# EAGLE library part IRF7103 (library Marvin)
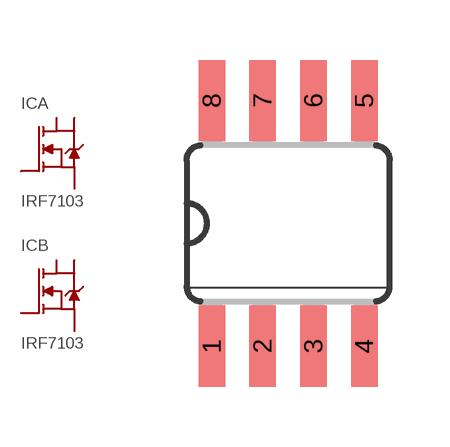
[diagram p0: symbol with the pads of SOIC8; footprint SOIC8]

Designator prefix IC; gates A=IRF7103 B=IRF7103

## IRF7103  [SOIC8]
1  A:S  pas
2  A:G  pas
3  B:S  pas
4  B:G  pas
5  B:D2  pas
6  B:D1  pas
7  A:D2  pas
8  A:D1  pas

## Footprint SOIC8 (pad centres in mm)
smd 0.66 x 2.032: 1 -1.905,-3.073; 2 -0.635,-3.073; 3 0.635,-3.073; 4 1.905,-3.073; 5 1.905,3.073; 6 0.635,3.073; 7 -0.635,3.073; 8 -1.905,3.073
